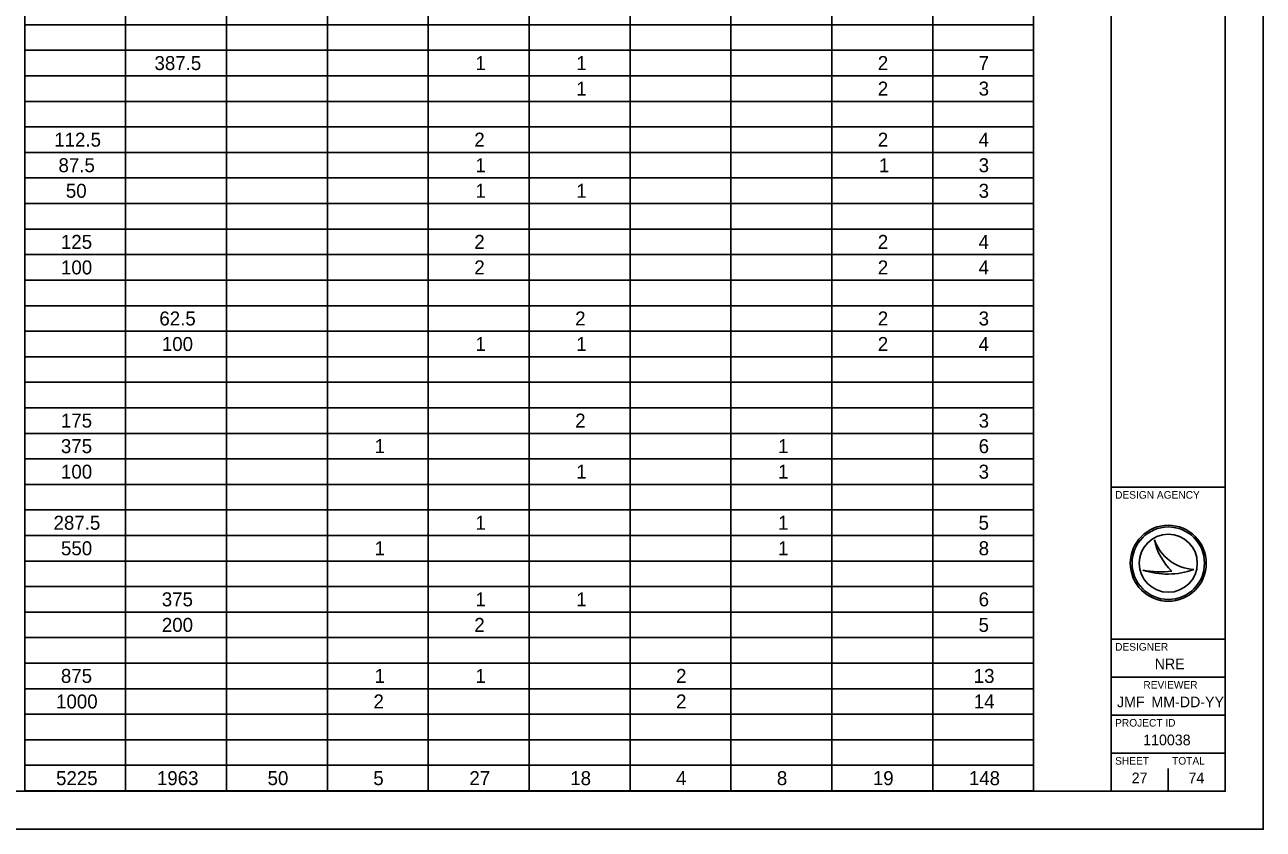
# Model space of a CAD drawing. Extents: x 0 to 34, y 0 to 22.
# Drawn here: x 17.69 to 34, y 0 to 10.59 of the extents above; entities that cross this region are included whole.
import ezdxf

# ---------------------------------------------------------------- set-up
doc = ezdxf.new("R2010")
doc.units = 0
for name, color, linetype in [('SH_Border', 7, 'Continuous'), ('SH_Cut_Line', 7, 'Continuous'), ('SH_Data', 7, 'Continuous'), ('SH_Text', 7, 'Continuous')]:
    doc.layers.add(name, color=color, linetype=linetype)

msp = doc.modelspace()

# ---------------------------------------------------------------- linework, layer by layer
at = {"layer": 'SH_Border'}
for p, q in [((32, 0.5), (32, 21.5)), ((32, 4.5), (33.5, 4.5)), ((32, 2.5), (33.5, 2.5)), ((32, 2), (33.5, 2)), ((32, 1.5), (33.5, 1.5)), ((32, 1), (33.5, 1))]:
    msp.add_line(p, q, dxfattribs=at)
msp.add_lwpolyline([(1.5, 21.5), (33.5, 21.5), (33.5, 0.5), (1.5, 0.5)], close=True, dxfattribs=at)
at = {"layer": 'SH_Cut_Line'}
msp.add_lwpolyline([(0, 0), (34, 0), (34, 22), (0, 22)], close=True, dxfattribs=at)
at = {"layer": 'SH_Data'}
for p, q in [((32.567, 3.81), (32.567, 3.81)), ((32.75, 3.5), (32.75, 3.5)), ((32.417, 3.41), (32.417, 3.41)), ((33.087, 3.419), (33.087, 3.419)), ((32.375, 0.675), (32.375, 0.675)), ((32.75, 0.5), (32.75, 0.8))]:
    msp.add_line(p, q, dxfattribs=at)
for radius in [0.5, 0.477, 0.477, 0.382]:
    msp.add_circle((32.75, 3.5), radius, dxfattribs=at)
for centre, radius, start, end in [((33.116, 3.998), 0.58, 198.9257, 198.9319), ((33.347, 3.97), 0.796, 191.6379, 191.6421), ((33.116, 3.998), 0.58, 198.9319, 267.1657), ((33.347, 3.97), 0.796, 191.6421, 226.0947), ((32.739, 4.37), 1.013, 251.4576, 290.0832), ((32.648, 4.654), 1.266, 259.4964, 259.4995), ((32.739, 4.37), 1.013, 251.4527, 251.4576), ((32.648, 4.654), 1.266, 259.4995, 276.6672)]:
    msp.add_arc(centre, radius, start, end, dxfattribs=at)
at = {"layer": 'SH_Text'}
for p, q in [((17.694, 11.594), (17.694, 10.586)), ((19.022, 11.594), (19.022, 10.586)), ((20.35, 11.594), (20.35, 10.586)), ((21.679, 11.594), (21.679, 10.586)), ((23.007, 11.594), (23.007, 10.586)), ((24.335, 11.594), (24.335, 10.586)), ((25.663, 11.594), (25.663, 10.586)), ((26.991, 11.594), (26.991, 10.586)), ((28.32, 11.594), (28.32, 10.586)), ((29.648, 11.594), (29.648, 10.586)), ((30.976, 11.594), (30.976, 10.586)), ((17.694, 10.586), (19.022, 10.586)), ((17.694, 10.586), (17.694, 9.914)), ((19.022, 10.586), (28.32, 10.586)), ((19.022, 10.586), (19.022, 9.914)), ((20.35, 10.586), (20.35, 9.914)), ((21.679, 10.586), (21.679, 9.914)), ((23.007, 10.586), (23.007, 9.914)), ((24.335, 10.586), (24.335, 9.914)), ((25.663, 10.586), (25.663, 9.914)), ((26.991, 10.586), (26.991, 9.914)), ((28.32, 10.586), (29.648, 10.586)), ((28.32, 10.586), (28.32, 9.914)), ((29.648, 10.586), (30.976, 10.586)), ((29.648, 10.586), (29.648, 9.914)), ((30.976, 10.586), (30.976, 9.914)), ((17.694, 10.25), (19.022, 10.25)), ((19.022, 10.25), (28.32, 10.25)), ((28.32, 10.25), (29.648, 10.25)), ((29.648, 10.25), (30.976, 10.25)), ((17.694, 9.914), (19.022, 9.914)), ((17.694, 9.914), (17.694, 8.906)), ((19.022, 9.914), (28.32, 9.914)), ((19.022, 9.914), (19.022, 8.906)), ((20.35, 9.914), (20.35, 8.906)), ((21.679, 9.914), (21.679, 8.906)), ((23.007, 9.914), (23.007, 8.906)), ((24.335, 9.914), (24.335, 8.906)), ((25.663, 9.914), (25.663, 8.906)), ((26.991, 9.914), (26.991, 8.906)), ((28.32, 9.914), (29.648, 9.914)), ((28.32, 9.914), (28.32, 8.906)), ((29.648, 9.914), (30.976, 9.914)), ((29.648, 9.914), (29.648, 8.906)), ((30.976, 9.914), (30.976, 8.906)), ((17.694, 9.578), (19.022, 9.578)), ((19.022, 9.578), (28.32, 9.578)), ((28.32, 9.578), (29.648, 9.578)), ((29.648, 9.578), (30.976, 9.578)), ((17.694, 9.242), (19.022, 9.242)), ((19.022, 9.242), (28.32, 9.242)), ((28.32, 9.242), (29.648, 9.242)), ((29.648, 9.242), (30.976, 9.242)), ((17.694, 8.906), (19.022, 8.906)), ((17.694, 8.906), (17.694, 8.233)), ((19.022, 8.906), (28.32, 8.906)), ((19.022, 8.906), (19.022, 8.233)), ((20.35, 8.906), (20.35, 8.233)), ((21.679, 8.906), (21.679, 8.233)), ((23.007, 8.906), (23.007, 8.233)), ((24.335, 8.906), (24.335, 8.233)), ((25.663, 8.906), (25.663, 8.233)), ((26.991, 8.906), (26.991, 8.233)), ((28.32, 8.906), (29.648, 8.906)), ((28.32, 8.906), (28.32, 8.233)), ((29.648, 8.906), (30.976, 8.906)), ((29.648, 8.906), (29.648, 8.233)), ((30.976, 8.906), (30.976, 8.233)), ((17.694, 8.57), (19.022, 8.57)), ((19.022, 8.57), (28.32, 8.57)), ((28.32, 8.57), (29.648, 8.57)), ((29.648, 8.57), (30.976, 8.57)), ((17.694, 8.233), (19.022, 8.233)), ((17.694, 8.233), (17.694, 7.225)), ((19.022, 8.233), (28.32, 8.233)), ((19.022, 8.233), (19.022, 7.225)), ((20.35, 8.233), (20.35, 7.225)), ((21.679, 8.233), (21.679, 7.225)), ((23.007, 8.233), (23.007, 7.225)), ((24.335, 8.233), (24.335, 7.225)), ((25.663, 8.233), (25.663, 7.225)), ((26.991, 8.233), (26.991, 7.225)), ((28.32, 8.233), (29.648, 8.233)), ((28.32, 8.233), (28.32, 7.225)), ((29.648, 8.233), (30.976, 8.233)), ((29.648, 8.233), (29.648, 7.225)), ((30.976, 8.233), (30.976, 7.225)), ((17.694, 7.897), (19.022, 7.897)), ((19.022, 7.897), (28.32, 7.897)), ((28.32, 7.897), (29.648, 7.897)), ((29.648, 7.897), (30.976, 7.897)), ((17.694, 7.561), (19.022, 7.561)), ((19.022, 7.561), (28.32, 7.561)), ((28.32, 7.561), (29.648, 7.561)), ((29.648, 7.561), (30.976, 7.561)), ((17.694, 7.225), (19.022, 7.225)), ((17.694, 7.225), (17.694, 6.553)), ((19.022, 7.225), (28.32, 7.225)), ((19.022, 7.225), (19.022, 6.553)), ((20.35, 7.225), (20.35, 6.553)), ((21.679, 7.225), (21.679, 6.553)), ((23.007, 7.225), (23.007, 6.553)), ((24.335, 7.225), (24.335, 6.553)), ((25.663, 7.225), (25.663, 6.553)), ((26.991, 7.225), (26.991, 6.553)), ((28.32, 7.225), (29.648, 7.225)), ((28.32, 7.225), (28.32, 6.553)), ((29.648, 7.225), (30.976, 7.225)), ((29.648, 7.225), (29.648, 6.553)), ((30.976, 7.225), (30.976, 6.553)), ((17.694, 6.889), (19.022, 6.889)), ((19.022, 6.889), (28.32, 6.889)), ((28.32, 6.889), (29.648, 6.889)), ((29.648, 6.889), (30.976, 6.889)), ((17.694, 6.553), (19.022, 6.553)), ((17.694, 6.553), (17.694, 5.545)), ((19.022, 6.553), (28.32, 6.553)), ((19.022, 6.553), (19.022, 5.545)), ((20.35, 6.553), (20.35, 5.545)), ((21.679, 6.553), (21.679, 5.545)), ((23.007, 6.553), (23.007, 5.545)), ((24.335, 6.553), (24.335, 5.545)), ((25.663, 6.553), (25.663, 5.545)), ((26.991, 6.553), (26.991, 5.545)), ((28.32, 6.553), (29.648, 6.553)), ((28.32, 6.553), (28.32, 5.545)), ((29.648, 6.553), (30.976, 6.553)), ((29.648, 6.553), (29.648, 5.545)), ((30.976, 6.553), (30.976, 5.545)), ((17.694, 6.217), (19.022, 6.217)), ((19.022, 6.217), (28.32, 6.217)), ((28.32, 6.217), (29.648, 6.217)), ((29.648, 6.217), (30.976, 6.217)), ((17.694, 5.881), (19.022, 5.881)), ((19.022, 5.881), (28.32, 5.881)), ((28.32, 5.881), (29.648, 5.881)), ((29.648, 5.881), (30.976, 5.881)), ((17.694, 5.545), (19.022, 5.545)), ((17.694, 5.545), (17.694, 4.873)), ((19.022, 5.545), (28.32, 5.545)), ((19.022, 5.545), (19.022, 4.873)), ((20.35, 5.545), (20.35, 4.873)), ((21.679, 5.545), (21.679, 4.873)), ((23.007, 5.545), (23.007, 4.873)), ((24.335, 5.545), (24.335, 4.873)), ((25.663, 5.545), (25.663, 4.873)), ((26.991, 5.545), (26.991, 4.873)), ((28.32, 5.545), (29.648, 5.545)), ((28.32, 5.545), (28.32, 4.873)), ((29.648, 5.545), (30.976, 5.545)), ((29.648, 5.545), (29.648, 4.873)), ((30.976, 5.545), (30.976, 4.873)), ((17.694, 5.209), (19.022, 5.209)), ((19.022, 5.209), (28.32, 5.209)), ((28.32, 5.209), (29.648, 5.209)), ((29.648, 5.209), (30.976, 5.209)), ((17.694, 4.873), (19.022, 4.873)), ((17.694, 4.873), (17.694, 3.865)), ((19.022, 4.873), (28.32, 4.873)), ((19.022, 4.873), (19.022, 3.865)), ((20.35, 4.873), (20.35, 3.865)), ((21.679, 4.873), (21.679, 3.865)), ((23.007, 4.873), (23.007, 3.865)), ((24.335, 4.873), (24.335, 3.865)), ((25.663, 4.873), (25.663, 3.865)), ((26.991, 4.873), (26.991, 3.865)), ((28.32, 4.873), (29.648, 4.873)), ((28.32, 4.873), (28.32, 3.865)), ((29.648, 4.873), (30.976, 4.873)), ((29.648, 4.873), (29.648, 3.865)), ((30.976, 4.873), (30.976, 3.865)), ((17.694, 4.537), (19.022, 4.537)), ((19.022, 4.537), (28.32, 4.537)), ((28.32, 4.537), (29.648, 4.537)), ((29.648, 4.537), (30.976, 4.537)), ((17.694, 4.201), (19.022, 4.201)), ((19.022, 4.201), (28.32, 4.201)), ((28.32, 4.201), (29.648, 4.201)), ((29.648, 4.201), (30.976, 4.201)), ((17.694, 3.865), (19.022, 3.865)), ((17.694, 3.865), (17.694, 3.193)), ((19.022, 3.865), (28.32, 3.865)), ((19.022, 3.865), (19.022, 3.193)), ((20.35, 3.865), (20.35, 3.193)), ((21.679, 3.865), (21.679, 3.193)), ((23.007, 3.865), (23.007, 3.193)), ((24.335, 3.865), (24.335, 3.193)), ((25.663, 3.865), (25.663, 3.193)), ((26.991, 3.865), (26.991, 3.193)), ((28.32, 3.865), (29.648, 3.865)), ((28.32, 3.865), (28.32, 3.193)), ((29.648, 3.865), (30.976, 3.865)), ((29.648, 3.865), (29.648, 3.193)), ((30.976, 3.865), (30.976, 3.193)), ((17.694, 3.529), (19.022, 3.529)), ((19.022, 3.529), (28.32, 3.529)), ((28.32, 3.529), (29.648, 3.529)), ((29.648, 3.529), (30.976, 3.529)), ((17.694, 3.193), (19.022, 3.193)), ((17.694, 3.193), (17.694, 0.504)), ((19.022, 3.193), (28.32, 3.193)), ((19.022, 3.193), (19.022, 0.504)), ((20.35, 3.193), (20.35, 0.504)), ((21.679, 3.193), (21.679, 0.504)), ((23.007, 3.193), (23.007, 0.504)), ((24.335, 3.193), (24.335, 0.504)), ((25.663, 3.193), (25.663, 0.504)), ((26.991, 3.193), (26.991, 0.504)), ((28.32, 3.193), (29.648, 3.193)), ((28.32, 3.193), (28.32, 0.504)), ((29.648, 3.193), (30.976, 3.193)), ((29.648, 3.193), (29.648, 0.504)), ((30.976, 3.193), (30.976, 0.504)), ((17.694, 2.857), (19.022, 2.857)), ((19.022, 2.857), (28.32, 2.857)), ((28.32, 2.857), (29.648, 2.857)), ((29.648, 2.857), (30.976, 2.857)), ((17.694, 2.521), (19.022, 2.521)), ((19.022, 2.521), (28.32, 2.521)), ((28.32, 2.521), (29.648, 2.521)), ((29.648, 2.521), (30.976, 2.521)), ((17.694, 2.185), (19.022, 2.185)), ((19.022, 2.185), (28.32, 2.185)), ((28.32, 2.185), (29.648, 2.185)), ((29.648, 2.185), (30.976, 2.185)), ((17.694, 1.849), (19.022, 1.849)), ((19.022, 1.849), (28.32, 1.849)), ((28.32, 1.849), (29.648, 1.849)), ((29.648, 1.849), (30.976, 1.849)), ((17.694, 1.513), (19.022, 1.513)), ((19.022, 1.513), (28.32, 1.513)), ((28.32, 1.513), (29.648, 1.513)), ((29.648, 1.513), (30.976, 1.513)), ((17.694, 1.177), (19.022, 1.177)), ((19.022, 1.177), (28.32, 1.177)), ((28.32, 1.177), (29.648, 1.177)), ((29.648, 1.177), (30.976, 1.177)), ((17.694, 0.841), (19.022, 0.841)), ((19.022, 0.841), (28.32, 0.841)), ((28.32, 0.841), (29.648, 0.841)), ((29.648, 0.841), (30.976, 0.841)), ((17.694, 0.504), (19.022, 0.504)), ((19.022, 0.504), (28.32, 0.504)), ((28.32, 0.504), (29.648, 0.504)), ((29.648, 0.504), (30.976, 0.504))]:
    msp.add_line(p, q, dxfattribs=at)

# ---------------------------------------------------------------- texts
at = {"layer": 'SH_Data'}
for s, height, p in [('DESIGN AGENCY', 0.1, (32.05, 4.35)), ('DESIGNER', 0.1, (32.05, 2.35)), ('NRE', 0.14, (32.571, 2.105)), ('REVIEWER', 0.1, (32.422, 1.85)), ('JMF', 0.14, (32.075, 1.605)), ('MM-DD-YY', 0.14, (32.527, 1.605)), ('PROJECT ID', 0.1, (32.05, 1.35)), ('110038', 0.14, (32.419, 1.105)), ('SHEET', 0.1, (32.05, 0.85)), ('TOTAL', 0.1, (32.8, 0.85)), ('27', 0.14, (32.268, 0.605)), ('74', 0.14, (33.016, 0.605))]:
    msp.add_text(s, height=height, dxfattribs=at).set_placement(p)
at = {"layer": 'SH_Text'}
for s, p in [('387.5', (19.402, 9.99)), ('1', (23.628, 9.99)), ('1', (24.956, 9.99)), ('2', (28.925, 9.99)), ('7', (30.253, 9.99)), ('1', (24.956, 9.654)), ('2', (28.925, 9.654)), ('3', (30.253, 9.654)), ('112.5', (18.082, 8.982)), ('2', (23.613, 8.982)), ('2', (28.925, 8.982)), ('4', (30.253, 8.982)), ('87.5', (18.138, 8.646)), ('1', (23.628, 8.646)), ('1', (28.941, 8.646)), ('3', (30.253, 8.646)), ('50', (18.235, 8.309)), ('1', (23.628, 8.309)), ('1', (24.956, 8.309)), ('3', (30.253, 8.309)), ('125', (18.17, 7.637)), ('2', (23.613, 7.637)), ('2', (28.925, 7.637)), ('4', (30.253, 7.637)), ('100', (18.171, 7.301)), ('2', (23.613, 7.301)), ('2', (28.925, 7.301)), ('4', (30.253, 7.301)), ('62.5', (19.466, 6.629)), ('2', (24.941, 6.629)), ('2', (28.925, 6.629)), ('3', (30.253, 6.629)), ('100', (19.499, 6.293)), ('1', (23.628, 6.293)), ('1', (24.956, 6.293)), ('2', (28.925, 6.293)), ('4', (30.253, 6.293)), ('175', (18.17, 5.285)), ('2', (24.941, 5.285)), ('3', (30.253, 5.285)), ('375', (18.17, 4.949)), ('1', (22.3, 4.949)), ('1', (27.612, 4.949)), ('6', (30.253, 4.949)), ('100', (18.171, 4.613)), ('1', (24.956, 4.613)), ('1', (27.612, 4.613)), ('3', (30.253, 4.613)), ('287.5', (18.073, 3.941)), ('1', (23.628, 3.941)), ('1', (27.612, 3.941)), ('5', (30.252, 3.941)), ('550', (18.171, 3.605)), ('1', (22.3, 3.605)), ('1', (27.612, 3.605)), ('8', (30.253, 3.605)), ('375', (19.498, 2.933)), ('1', (23.628, 2.933)), ('1', (24.956, 2.933)), ('6', (30.253, 2.933)), ('200', (19.499, 2.597)), ('2', (23.613, 2.597)), ('5', (30.252, 2.597)), ('875', (18.17, 1.925)), ('1', (22.3, 1.925)), ('1', (23.628, 1.925)), ('2', (26.269, 1.925)), ('13', (30.188, 1.925)), ('1000', (18.106, 1.589)), ('2', (22.285, 1.589)), ('2', (26.269, 1.589)), ('14', (30.189, 1.589)), ('5225', (18.106, 0.58)), ('1963', (19.434, 0.58)), ('50', (20.891, 0.58)), ('5', (22.283, 0.58)), ('27', (23.548, 0.58)), ('18', (24.876, 0.58)), ('4', (26.269, 0.58)), ('8', (27.596, 0.58)), ('19', (28.86, 0.58)), ('148', (30.124, 0.58))]:
    msp.add_text(s, height=0.184, dxfattribs=at).set_placement(p)

doc.saveas('drawing.dxf')
